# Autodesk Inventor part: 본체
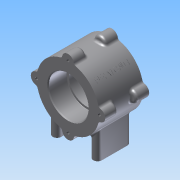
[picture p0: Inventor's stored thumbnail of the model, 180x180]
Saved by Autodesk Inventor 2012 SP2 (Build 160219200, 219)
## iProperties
Created: 2015-03
Part Number: 본체
Material: Default
Document SubType Name: Modeling
Designer: Administrator
Density: 1 g/cm^3
Author: Administrator
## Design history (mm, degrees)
sketch "스케치2"
  geometry: L1 (-26, 0)-(26, 0); L2 (-26, 0)-(-26, 37); L3 (-26, 37)-(26, 37); L4 (26, 37)-(26, 0); 2 further points
  constraints: 8 end point, 3 perpendicular, 2 coincident, 1 horizontal, 1 midpoint
  dimensions: "d1" = 52 distance of L1.start L1.end; "d2" = 74 diameter of L3 L1
revolve "회전1" sketch "스케치2" stored, may be unused: angle "d3" = 90 deg
sketch "스케치8"
  geometry: L1 (37, -26)-(-37, -26) reference; L2 (-37, -26)-(-37, 26) reference; L3 (-37, 26)-(37, 26) reference; L4 (37, 26)-(37, -26) reference; L5 (0, 26)-(0, -26); L6 (-29, 15)-(-29, -15); L7 (-29, -15)-(-19, -15); L8 (-19, -15)-(-19, 15); L9 (-19, 15)-(-29, 15); L10 (19, 15)-(19, -15); L11 (19, -15)-(29, -15); L12 (29, -15)-(29, 15); L13 (29, 15)-(19, 15); L14 (-37, 0)-(37, 0); A1 r 5 centre (-24, 15) between (-19, 15) and (-29, 15); A2 r 5 centre (24, 15) between (29, 15) and (19, 15); A3 r 5 centre (24, -15) between (19, -15) and (29, -15); A4 r 5 centre (-24, -15) between (-29, -15) and (-19, -15); 1 further point
  constraints: 20 end point, 8 midpoint, 8 point on circle, 4 centre point, 4 horizontal, 2 vertical, 1 parallel, 1 perpendicular, 3 other
  dimensions: "d42" = 38 distance between parallel lines of L8 L10; "d43" = 10 distance between parallel lines of L8 L6; "d44" = 10 distance between parallel lines of L12 L10; "d45" = 30 distance of A4.centre A1.centre; "d46" = 30 distance between parallel lines of L13 L11
extrude "돌출2" join sketch "스케치8" distance "d47" = 56; taper "d48" = 0 deg
sketch "스케치4"
  geometry: L1 (-26, -37)-(-26, 37) reference; L2 (-26, 37)-(26, 37) reference; L3 (26, 37)-(26, -37) reference; L4 (26, -37)-(-26, -37) reference; L5 (-25.085, 37)-(26, 37); L6 (-26, 37)-(-26, 44); L7 (-26, 44)-(-14, 44); L8 (-11, 41)-(-11, 37); L9 (26, 37)-(26, 44); L10 (26, 44)-(14, 44); L11 (11, 41)-(11, 37); A1 r 3 centre (-14, 41) between (-11, 41) and (-14, 44); A2 r 3 centre (14, 41) between (14, 44) and (11, 41); 3 further points
  constraints: 14 end point, 7 point on line, 6 perpendicular, 4 point on circle, 4 tangent, 2 centre point, 1 equal radius, 1 horizontal alignment, 1 parallel
  dimensions: "d10" = 14 diameter of L7 L2; "d11" = 15 distance between parallel lines of L6 L8; "d12" = 15 distance between parallel lines of L9 L11; "d13" = 3 radius of A1
revolve "회전2" sketch "스케치4" stored, may be unused: angle "d14" = 90 deg
sketch "스케치5"
  geometry: L1 (-11, 41)-(-11, 37) reference; L2 (-11, 37)-(11, 37) reference; L3 (11, 37)-(11, 41) reference; L4 (14, 44)-(26, 44) reference; L5 (26, 44)-(26, -44) reference; L6 (26, -44)-(14, -44) reference; L7 (11, -41)-(11, -37) reference; L8 (11, -37)-(-11, -37) reference; L9 (-11, -37)-(-11, -41) reference; L10 (-14, -44)-(-26, -44) reference; L11 (-26, -44)-(-26, 44) reference; L12 (-26, 44)-(-14, 44) reference; L13 (-26, 0)-(26, 0); L14 (-25, 23.5)-(-4.3, 23.5); L15 (-4, 23.2)-(-4, 21); L16 (-4, 21)-(4, 21); L17 (4, 21)-(4, 23.2); L18 (4.3, 23.5)-(25, 23.5); L19 (-25, 23.5)-(-26, 24.5); L20 (25, 23.5)-(26, 24.5); L21 (-26, 24.5)-(-26, 0); L22 (26, 0)-(26, 24.5); A1 r 3 centre (-14, 41) between (-11, 41) and (-14, 44) reference; A2 r 3 centre (14, 41) between (14, 44) and (11, 41) reference; A3 r 3 centre (14, -41) between (11, -41) and (14, -44) reference; A4 r 3 centre (-14, -41) between (-14, -44) and (-11, -41) reference; A5 r 0.3 centre (-4.3, 23.2) between (-4, 23.2) and (-4.3, 23.5); A6 r 0.3 centre (4.3, 23.2) between (4.3, 23.5) and (4, 23.2); 5 further points
  constraints: 20 end point, 10 point on line, 4 parallel, 4 point on circle, 4 tangent, 2 centre point, 2 midpoint, 2 perpendicular, 1 collinear, 1 equal radius, 1 horizontal alignment
  dimensions: "d18" = 22 distance between parallel lines of L11 L15; "d19" = 22 distance between parallel lines of L5 L17; "d20" = 47 diameter of L14 L13; "d21" = 42 diameter of L16 L13; "d22" = 0.3 radius of A5; "d23" = 1 distance of L14.start point (-26, 23.5); "d24" = 45 deg angle of L14 L19; "d25" = 1 distance of L18.end point (26, 23.5); "d26" = 45 deg angle of L18 L20
revolve "회전3" sketch "스케치5" stored, may be unused: angle "d27" = 90 deg
sketch "스케치6"
  geometry: A1 r 7 centre (0, -74) between (-6.969, -73.338) and (6.969, -73.338) reference; A2 r 7 centre (37, -37) between (36.338, -43.969) and (36.338, -30.031) reference; A3 r 7 centre (0, 0) between (6.969, -0.662) and (-6.969, -0.662) reference; A4 r 7 centre (-37, -37) between (-36.338, -30.031) and (-36.338, -43.969) reference; 4 further points
  constraints: 4 coincident
hole "구멍1" sketch "스케치6" at (0, 0), (37, -37), (0, -74), (-37, -37) diameter "d28" = 3.242; stored, may be unused: countersink angle "d32" = 90 deg, drill point angle "d34" = 118 deg; dims "d29" = 8, "d30" = 4, "d31" = 2, "d33" = 11
sketch "스케치7"
  geometry: A1 r 7 centre (0, 0) between (-6.969, 0.662) and (6.969, 0.662) reference; A2 r 7 centre (37, 37) between (36.338, 30.031) and (36.338, 43.969) reference; A3 r 7 centre (0, 74) between (6.969, 73.338) and (-6.969, 73.338) reference; A4 r 7 centre (-37, 37) between (-36.338, 43.969) and (-36.338, 30.031) reference; 4 further points
  constraints: 4 coincident
hole "구멍2" sketch "스케치7" at (0, 74), (37, 37), (0, 0), (-37, 37) diameter "d35" = 3.242; stored, may be unused: countersink angle "d39" = 90 deg, drill point angle "d41" = 118 deg; dims "d36" = 8, "d37" = 4, "d38" = 2, "d40" = 11
sketch "스케치9"
  geometry: L1 (-29, -15)-(-29, 15) reference; L2 (-19, 15)-(-19, -15) reference; L3 (19, -15)-(19, 15) reference; L4 (29, 15)-(29, -15) reference; A1 r 5 centre (-24, 15) between (-19, 15) and (-29, 15) reference; A2 r 5 centre (-24, -15) between (-29, -15) and (-19, -15) reference; A3 r 5 centre (24, 15) between (29, 15) and (19, 15) reference; A4 r 5 centre (24, -15) between (19, -15) and (29, -15) reference; 5 further points
  constraints: 4 coincident
hole "구멍3" sketch "스케치9" at (-24, 15), (24, 15), (24, -15), (-24, -15) diameter "d49" = 4.134; stored, may be unused: countersink angle "d53" = 90 deg, drill point angle "d55" = 118 deg; dims "d50" = 6, "d51" = 4, "d52" = 2, "d54" = 8
fillet "모깎기1" dims "d56" = 3
node "작업 평면2"
sketch "스케치11"
  geometry: L1 (0, -18.921)-(0, 18.921) reference; 2 further points
  constraints: 1 coincident, 1 other
  dimensions: "d59" = 26 distance from line of L1 point (26, 0)
feature "엠보싱1" sketch "스케치11" dims "d1" = 52, "d2" = 74, "d60" = 0.5, "d61" = 0
node "솔리드1"
pattern_circular "원형 패턴1" dims angle "d16" = 360 deg
node "절단 모서리 투영2"
node "절단 모서리 투영3"
node "절단 모서리 투영4"
node "절단 모서리 투영5"
